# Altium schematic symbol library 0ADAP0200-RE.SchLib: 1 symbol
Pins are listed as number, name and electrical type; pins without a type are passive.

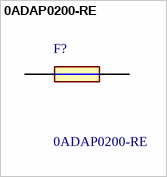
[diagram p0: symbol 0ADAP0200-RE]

## 0ADAP0200-RE
designator F?
Fuses with Leads (Through Hole) FUSE, CERAMIC TUBE 0.2A 600VAC600VDC; Manufacturer_Name: BelFuse; Geometry.Height: 7.06mm
footprint 0ADAP0200RE
pins: 1, 2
